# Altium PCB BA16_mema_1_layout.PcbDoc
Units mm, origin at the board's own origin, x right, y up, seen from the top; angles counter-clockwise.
Board outline 42 x 70 mm, 2 copper layers (Top Layer, Bottom Layer); 44 components, 23 nets, 138 pads, 178 vias.
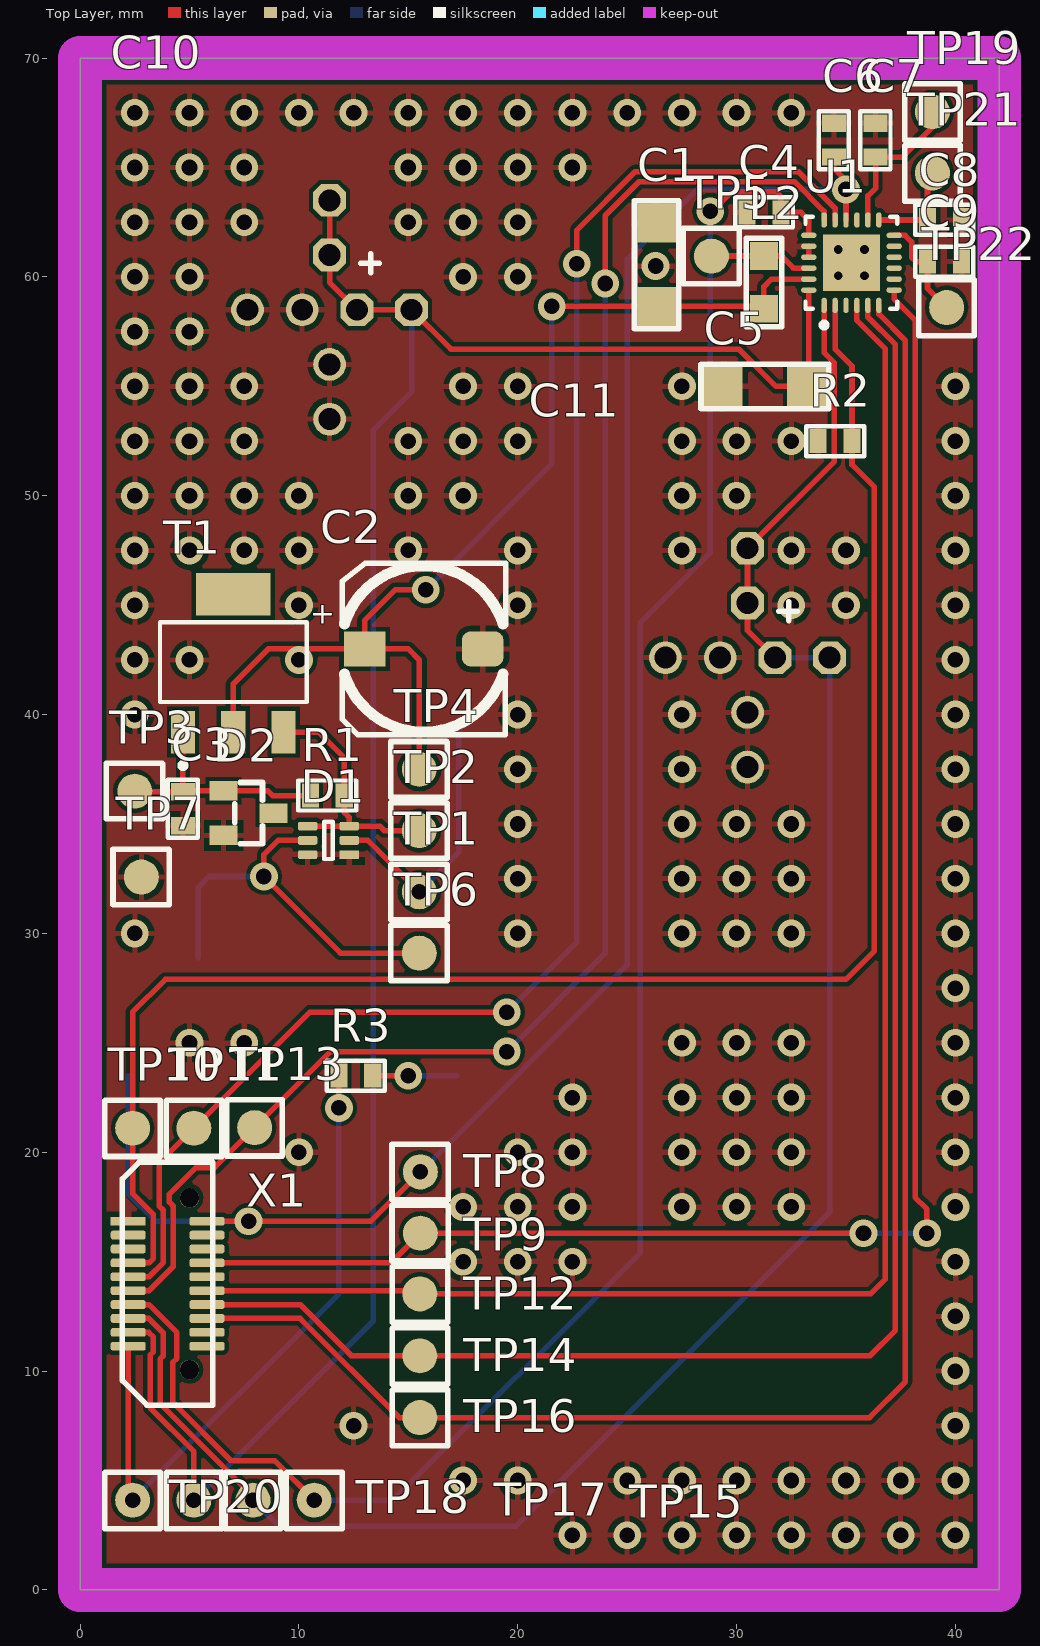
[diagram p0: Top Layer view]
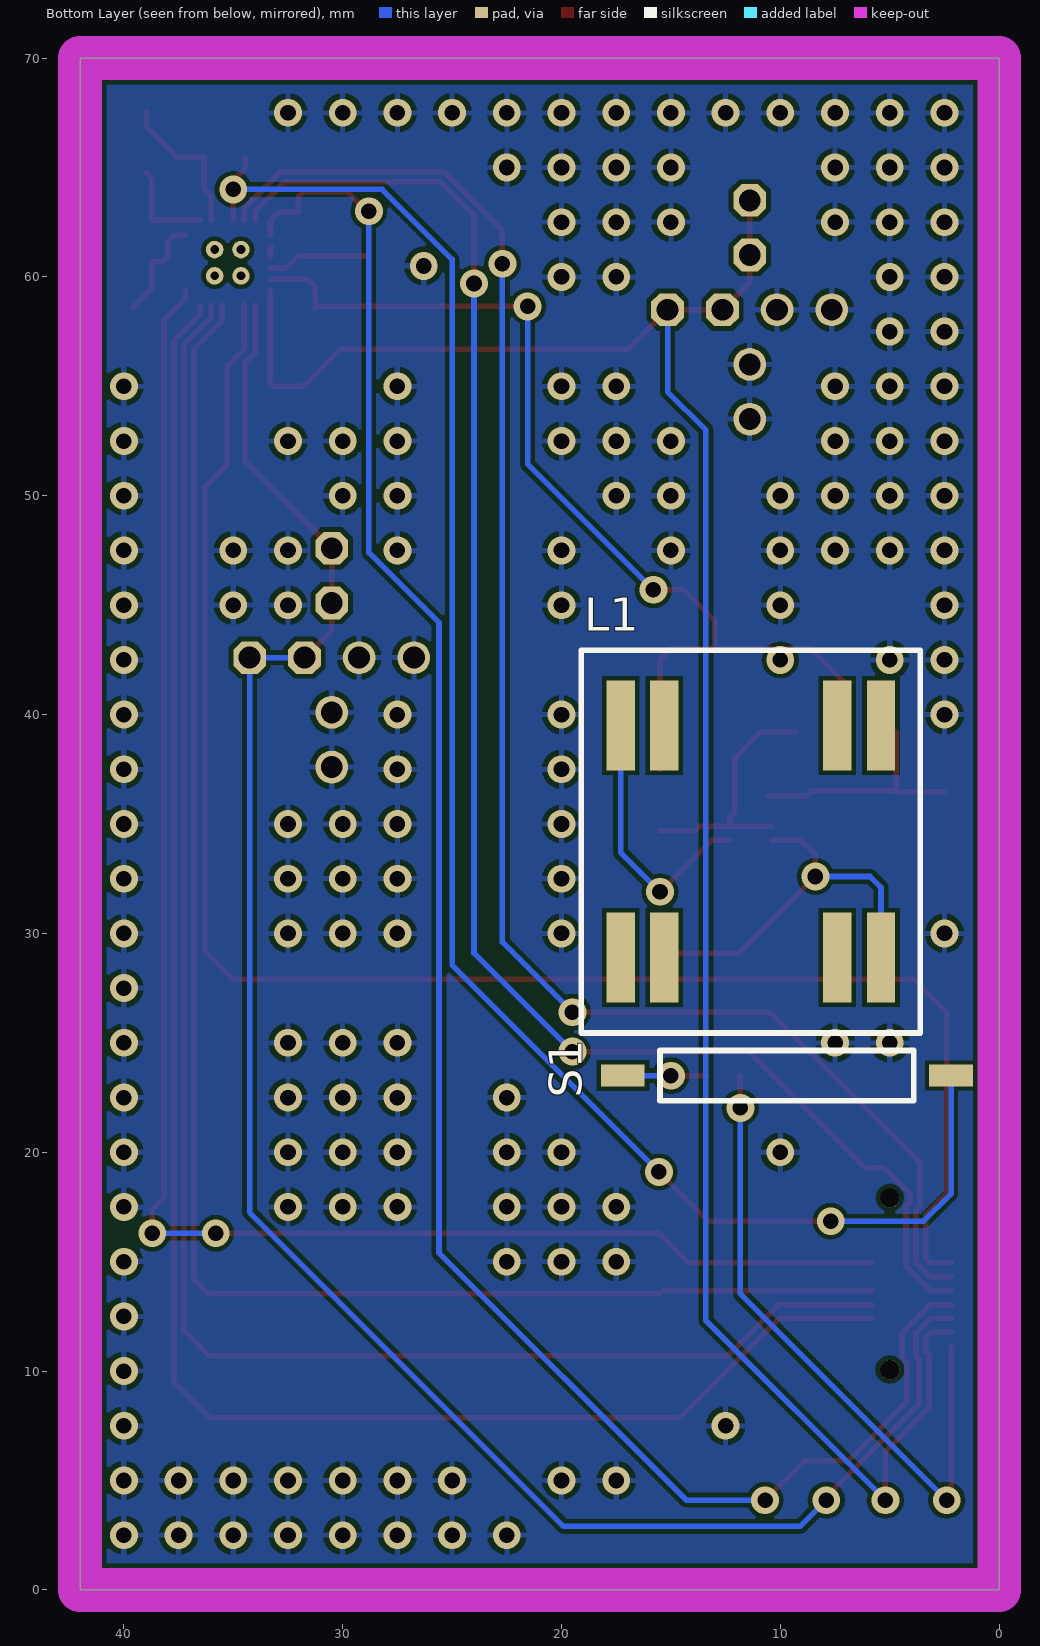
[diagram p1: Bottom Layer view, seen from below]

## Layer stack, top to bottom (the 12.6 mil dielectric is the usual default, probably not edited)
Top Solder: solder mask 0.0102, Solder Resist, Dk 3.5
Top Layer: signal copper 0.0356
Dielectric 1: dielectric 0.32, FR-4, Dk 4.8
Bottom Layer: signal copper 0.0356
Bottom Solder: solder mask 0.0102, Solder Resist, Dk 3.5

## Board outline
0,0 0,70 42,70 42,0

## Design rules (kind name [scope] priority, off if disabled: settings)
Clearance Clearance_EM8500 [All] p1: gap=0.2
Clearance [All] p2: gap=0.254
ComponentClearance ComponentClearance_ELKO_FLEX [HasFootprint('C_RAD_flex')] p1: gap=-5 collisioncheckmode=3 verticalgap=0.254 showdistances=FALSE
ComponentClearance ComponentClearance_TP [HasFootprint('TP SMD')] p2: gap=0 collisioncheckmode=3 verticalgap=0 showdistances=FALSE
ComponentClearance [All] p3: gap=0.254 collisioncheckmode=3 verticalgap=0.254 showdistances=FALSE
PolygonConnect [All] p1: connectstyle=Relief reliefconductorwidth=0.254 reliefentries=4 polygonreliefangle="90 Angle" airgapwidth=0.254
RoutingVias [All] p1: holewidth=0.711 width=1.27 viastyle="Through Hole" minholewidth=0.711 minwidth=1.27 maxholewidth=0.711 maxwidth=1.27
SilkToSilkClearance SilkToSilkClearance_TP [HasFootprint('TP SMD')] p1: silktosilkclearance=0
SilkToSilkClearance [All] p2: silktosilkclearance=0.254
SolderMaskExpansion [All] p1: expansion=0.102
Width [All] p1: maxlimit=0.254 minlimit=0.254 preferedwidth=0.254
28 further rules are at their usual default settings.

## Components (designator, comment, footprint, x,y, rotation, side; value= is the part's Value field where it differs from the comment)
C1 "Cap" "CHIP 1206" 26.35,58.65 r90 top
C2 "47uF 25V" "ELKO SMD-C 6.3x6.3" 15.7,43 r0 top
C3 "1nF" "CHIP 0603" 4.7,35.7 r90 top
C4 "Cap" "CHIP 0603" 31.25,62.95 r180 top
C5 "Cap" "CHIP 1206" 33.2,55 r180 top
C6 "Cap" "CHIP 0603" 34.45,66.25 r90 top
C7 "Cap" "CHIP 0603" 36.35,66.25 r90 top
C8 "Cap" "CHIP 0603" 39.5,62.6 r0 top
C9 "Cap" "CHIP 0603" 39.5,60.7 r0 top
C10 "3300uF 25V" C_RAD_FLEX 11.4,58.5 r0 top
C11 "470uF 25V" C_RAD_FLEX 30.5,42.6 r0 top
D1 "HSMS-286P" "SOT-363 (SC-70)" 12.3,33.6 r180 top
D2 "BAS16" SOT-23 7.7,35.5 r270 top
L1 "X-Wicklung" PREMO_3115N_0238J_2 17.3,28.9 r90 bottom
L2 "L" "CHIP 0805" 31.25,59.75 r270 top
R1 "1M" "CHIP 0603" 11.3,36.3 r0 top
R2 "R" "CHIP 0603" 34.5,52.5 r180 top
R3 "10k 0603" "CHIP 0603" 12.6,23.5 r0 top
S1 "Reed Switch" MK16-C-2 9.7,23.5 r180 bottom
T1 "BSP149" SOT-223 4.7,39.2 r0 top
TP1 "TP_SMD" "TP SMD" 15.5,31.9 r0 top
TP2 "TP_SMD" "TP SMD" 15.5,34.7 r0 top
TP3 "TP_SMD" "TP SMD" 2.5,36.5 r0 top
TP4 "TP_SMD" "TP SMD" 15.5,37.5 r0 top
TP5 "TP_SMD" "TP SMD" 28.85,60.95 r0 top
TP6 "TP_SMD" "TP SMD" 15.5,29.1 r0 top
TP7 "TP_SMD" "TP SMD" 2.8,32.575 r0 top
TP8 "TP_SMD" "TP SMD" 15.55,19.1 r0 top
TP9 "TP_SMD" "TP SMD" 15.55,16.3 r0 top
TP10 "TP_SMD" "TP SMD" 2.4,21.1 r90 top
TP11 "TP_SMD" "TP SMD" 5.2,21.1 r90 top
TP12 "TP_SMD" "TP SMD" 15.525,13.525 r90 top
TP13 "TP_SMD" "TP SMD" 7.975,21.125 r90 top
TP14 "TP_SMD" "TP SMD" 15.525,10.7 r90 top
TP15 "TP_SMD" "TP SMD" 10.7,4.1 r90 top
TP16 "TP_SMD" "TP SMD" 15.525,7.875 r90 top
TP17 "TP_SMD" "TP SMD" 7.9,4.1 r90 top
TP18 "TP_SMD" "TP SMD" 5.2,4.1 r90 top
TP19 "TP_SMD" "TP SMD" 38.95,67.55 r90 top
TP20 "TP_SMD" "TP SMD" 2.4,4.1 r90 top
TP21 "TP_SMD" "TP SMD" 38.95,64.75 r90 top
TP22 "TP_SMD" "TP SMD" 39.6,58.6 r90 top
U1 "em8500" QFN-24 35.25,60.65 r90 top
X1 "LSS-110-01-F-DV-A-TR" "HEADER SMD 2X10 0.635MM" 2.2,16.85 r0 top locked

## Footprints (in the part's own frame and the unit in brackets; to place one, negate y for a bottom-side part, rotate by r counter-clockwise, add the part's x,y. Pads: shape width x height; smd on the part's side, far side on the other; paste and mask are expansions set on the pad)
C_RAD_FLEX [mm] "KONDENSATOR, AXIAL, Raster 5"
  oct 1.5x1.5 hole 1: 1(0,2.5) 1(0,5) 1(1.25,0) 1(3.75,0)
  round 1.5 hole 1: 2(-3.75,0) 2(-1.25,0) 2(0,-5) 2(0,-2.5)
  silkscreen extent 1.42,1.7 2.27,2.55
"CHIP 0603" [mil] "Chip 0603 Body 1.6x0.8mm"
  rect 31x43 smd: 1(-30.5,0) 2(30.5,0)
  silkscreen extent -52,-27 52,27
"CHIP 0805" [mil] "Chip 0805 Body 2.0x1.2mm"
  rect 50x50 smd: 1(-47.5,0) 2(47.5,0)
  silkscreen extent -80,-32 80,32
"CHIP 1206" [mil] "Chip 1206 Body 3.2x1.6mm"
  rect 70x70 smd: 1(0,0) 2(150,0)
  silkscreen extent -40,-40 190,40
"ELKO SMD-C 6.3x6.3" [mm] "Elko SMD Size C 6.3x6.3mm H = 5.5mm"
  rect 1.9x1.6 smd: 1(-2.7,0)
  rrect50% 1.9x1.6 smd: 2(2.7,0)
  silkscreen extent -3.72,-3.93 3.75,3.93
"HEADER SMD 2X10 0.635MM" [mm] "LSS-110-01-F-DV-A"
  round 0.89 hole 0.89 unplated: 0(2.8,-6.783) 0(2.8,1.068)
  rect 1.6x0.4 smd: 1(0,0)
  rrect50% 1.6x0.4 smd: 2(3.6,0) 3(0,-0.635) 4(3.6,-0.635) 5(0,-1.27) 6(3.6,-1.27) 7(0,-1.905) 8(3.6,-1.905) 9(0,-2.54) 10(3.6,-2.54) 11(0,-3.175) 12(3.6,-3.175) 13(0,-3.81) 14(3.6,-3.81) 15(0,-4.445) 16(3.6,-4.445) 17(0,-5.08) 18(3.6,-5.08) 19(0,-5.715) 20(3.6,-5.715)
  silkscreen extent -0.27,-8.4 3.87,2.69
MK16-C-2 [mm] "REED SENSOR"
  rect 2x1 smd: 1(-7.5,0) 2(7.5,0)
  silkscreen extent -5.8,-1.15 5.8,1.15
PREMO_3115N_0238J_2 [mm] "3D Coil 15x15 2.38mH +/-5% @125kHz"
  rect 4.1x1.3 smd: 1(0,0) 2(0,-2) 3(0,-9.9) 4(0,-11.9) 5(10.6,-11.9) 6(10.6,-9.9) 7(10.6,-2) 8(10.6,0)
  silkscreen extent -3.45,-13.7 14.05,1.8
QFN-24 [mm] "24-Pin Plastic Quad Flat No-Lead 0.5 mm Pitch"
  oval 0.7x0.25 smd: 1(-1.95,1.25) 2(-1.95,0.75) 3(-1.95,0.25) 4(-1.95,-0.25) 5(-1.95,-0.75) 6(-1.95,-1.25) 13(1.95,-1.25) 14(1.95,-0.75) 15(1.95,-0.25) 16(1.95,0.25) 17(1.95,0.75) 18(1.95,1.25)
  oval 0.25x0.7 smd: 7(-1.25,-1.95) 8(-0.75,-1.95) 9(-0.25,-1.95) 10(0.25,-1.95) 11(0.75,-1.95) 12(1.25,-1.95) 19(1.25,1.95) 20(0.75,1.95) 21(0.25,1.95) 22(-0.25,1.95) 23(-0.75,1.95) 24(-1.25,1.95)
  round 0.8 hole 0.4: 25(-0.6,-0.6) 25(-0.6,0.6) 25(0.6,-0.6) 25(0.6,0.6)
  rect 2.6x2.6 smd: 25(0,0)
  silkscreen extent -2.97,-2.1 2.1,2.1, body extent -2.07,-2.07 2.07,2.07, height 1
SOT-23 [mil]
  rect 35x50 smd: 1(-40,-45) 2(40,-45) 3(0,45)
  silkscreen extent -55,-25 55,25
SOT-223 [mm] "SOT-223/SC-73; 4 Leads; Body 6.7 x 7.3 mm, inc. leads (LxW max)"
  rect 1.1x1.95 smd: 1(0,0) 2(2.3,0) 3(4.6,0)
  rect 3.4x1.95 smd: 4(2.3,6.3)
  silkscreen extent -1.05,-1.65 5.65,5.02
"SOT-363 (SC-70)" [mm]
  rect 0.9x0.4 smd: 1(0,0)
  rrect50% 0.9x0.4 smd: 2(0,-0.65) 3(0,-1.3) 4(1.9,-1.3) 5(1.9,-0.65) 6(1.9,0)
  silkscreen extent 0.75,-1.5 1.15,0.2
"TP SMD" [mm] "Testpoint SMD"
  round 1.6 smd: 1(0,0)
  silkscreen extent -1.3,-1.27 1.27,1.27

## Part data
C1 C4 C5 C6 C7 C8 C9: library part C, "Capacitor"
C2 C10 C11: library part "C POL", "Capasitor Polarisiert"
C3: library part "C 50V", "Capacitor 50V"
D1: "Diode Schottky Quadro"
D2: library part D, "Diode"
L1: library part "PREMO 3015 0238J 2", "Inductor"
L2: "Ind"
R1 R3: library part R, "Resistor"
R2: "Resistor"
S1: library part "SWITCH MICRO NO", "Switch Micro Normal Open"
T1: "MOSFET N-Kanal"
TP1 TP2 TP3 TP4 TP5 TP6 TP7 TP8 TP9 TP10 TP11 TP12 TP13 TP14 TP15 TP16 TP17 TP18 TP19 TP20 TP21 TP22: "Testpoint SMD"
X1: library part "HDR 20 POL ABW", "Header 100 mil 20 Pol"

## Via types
v1: diameter 1.27, hole 0.711, Top Layer to Bottom Layer, 178 vias

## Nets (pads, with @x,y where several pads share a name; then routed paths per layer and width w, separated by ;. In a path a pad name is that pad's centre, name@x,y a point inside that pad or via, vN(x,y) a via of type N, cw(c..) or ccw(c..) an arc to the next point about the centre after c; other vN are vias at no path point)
BAT_LOW: TP13.1 U1.18 X1.11 | length 75.7
  Top Layer w0.254: X1.11 3.159,13.675 4.258,14.774 4.258,17.539 4.079,17.718 4.079,18.088 5.291,19.3 6.15,19.3 TP13.1 11.45,24.6 v1(19.5,24.6) ; v1(24,59.7) 24,62.8 25.551,64.351 32.646,64.351 34,62.997 U1.18
  Bottom Layer w0.254: v1(19.5,24.6) 24,29.1 v1(24,59.7)
EM_CS: TP9.1 U1.7 X1.8 | length 77.2
  Top Layer w0.254: X1.8 14.195,14.945 TP9.1 v1(35.8,16.3) ; U1.7 37.2,59 38.162,58.038 38.162,17.938 38.7,17.4 v1(38.7,16.3)
  Bottom Layer w0.254: v1(35.8,16.3) v1(38.7,16.3)
GND: C1.2 C2.2 C3.1 C4.2 C5.2 C6.2 C7.2 C8.2 C9.2 C10.2 C11.2 D1.1 D1.6 D2.2 R2.2 TP7.1 U1.20 U1.21 X1.1 | length 0.5
  Top Layer w0.254: U1.21 U1.20
  other v1: 22.5,2.5 25,2.5 27.5,2.5 30,2.5 32.5,2.5 35,2.5 37.5,2.5 40,2.5 17.5,5 20,5 25,5 27.5,5 30,5 32.5,5 35,5 37.5,5 40,5 12.5,7.5 40,7.5 40,10 40,12.5 17.5,15 20,15 22.5,15 40,15 17.5,17.5 20,17.5 22.5,17.5 27.5,17.5 30,17.5 32.5,17.5 40,17.5 10,20 20,20 22.5,20 27.5,20 30,20 32.5,20 40,20 22.5,22.5 27.5,22.5 30,22.5 32.5,22.5 40,22.5 5,25 7.5,25 27.5,25 27.5,25 30,25 32.5,25 40,25 40,25 40,27.5 2.5,30 20,30 27.5,30 30,30 32.5,30 40,30 20,32.5 27.5,32.5 30,32.5 32.5,32.5 40,32.5 20,35 27.5,35 30,35 32.5,35 40,35 40,35 40,35 20,37.5 27.5,37.5 40,37.5 2.5,40 20,40 27.5,40 40,40 2.5,42.5 5,42.5 40,42.5 2.5,45 10,45 20,45 32.5,45 35,45 40,45 2.5,47.5 5,47.5 7.5,47.5 10,47.5 15,47.5 20,47.5 27.5,47.5 32.5,47.5 35,47.5 40,47.5 2.5,50 2.5,50 5,50 7.5,50 10,50 15,50 17.5,50 27.5,50 30,50 40,50 2.5,52.5 5,52.5 7.5,52.5 15,52.5 17.5,52.5 20,52.5 27.5,52.5 30,52.5 32.5,52.5 40,52.5 2.5,55 5,55 7.5,55 17.5,55 20,55 27.5,55 40,55 2.5,57.5 5,57.5 2.5,60 5,60 17.5,60 20,60 26.3,60.5 2.5,62.5 5,62.5 7.5,62.5 15,62.5 17.5,62.5 20,62.5 2.5,65 5,65 7.5,65 15,65 17.5,65 20,65 22.5,65 2.5,67.5 5,67.5 7.5,67.5 10,67.5 12.5,67.5 15,67.5 17.5,67.5 20,67.5 22.5,67.5 25,67.5 27.5,67.5 30,67.5 32.5,67.5
HRV_LOW: TP11.1 U1.17 X1.9 | length 76.4
  Top Layer w0.254: X1.9 3.152,14.31 3.804,14.962 3.804,17.35 3.625,17.529 3.625,19.525 TP11.1 10.5,26.4 v1(19.5,26.4) ; v1(22.7,60.6) 22.7,62.142 25.363,64.805 32.834,64.805 34.5,63.14 U1.17
  Bottom Layer w0.254: v1(19.5,26.4) 22.7,29.6 v1(22.7,60.6)
MCU_MISO: TP14.1 U1.5 X1.14 | length 80.3
  Top Layer w0.254: X1.14 10.06,13.04 12.4,10.7 TP14.1 36.1,10.7 37.254,11.854 37.254,56.904 36,58.158 U1.5
MCU_MOSI: TP12.1 U1.4 X1.12 | length 76.2
  Top Layer w0.254: X1.12 TP12.1@15.375,13.675 ; TP12.1 36.125,13.525 36.8,14.2 36.8,56.716 35.5,58.016 U1.4
MCU_SCLK: TP16.1 U1.6 X1.16 | length 84.2
  Top Layer w0.254: X1.16 10.053,12.405 14.583,7.875 TP16.1 36.075,7.875 37.708,9.508 37.708,57.092 36.5,58.3 U1.6
NetC3_2: C3.2 D2.1 R1.1 T1.1 TP3.1 | length 10.8
  Top Layer w0.254: TP3.1@2.525,36.475 C3.2 T1.1 ; C3.2@4.741,36.516 D2.1 8.584,36.516 8.8,36.3 R1.1
NetD1_2: D1.2 L1.8 TP1.1 | length 12.5
  Top Layer w0.254: D1.2 13.15,34.25 v1(15.5,31.9)
  Bottom Layer w0.254: v1(15.5,31.9) 17.3,33.7 L1.8
NetD1_3: D1.3 D1.4 R1.2 T1.3 TP2.1 | length 11.7
  Top Layer w0.254: T1.3 10.9,39.2 12.075,38.025 R1.2 12.075,35.525 12.3,35.3 D1.3 ; D1.4 D1.3 ; TP2.1 13.9,34.7 13.7,34.9 D1.3
NetD1_5: D1.5 L1.4 TP6.1 | length 18.2
  Top Layer w0.254: D1.5 9.05,34.25 8.4,33.6 v1(8.4,32.6) 11.9,29.1 TP6.1
  Bottom Layer w0.254: L1.4 5.4,32.1 5.9,32.6 v1(8.4,32.6)
NetL2_1: L2.1 TP5.1 U1.22 | length 4.7
  Top Layer w0.254: TP5.1@28.857,60.956 L2.1 32.044,60.956 32.6,60.4 U1.22
NetR3_2: R3.2 S1.1 | length 3.8
  Top Layer w0.254: R3.2 v1(15,23.5)
  Bottom Layer w0.254: v1(15,23.5) S1.1
REED_SWITCH: R3.1 TP20.1 X1.19 | length 30.1
  Top Layer w0.254: TP20.1@2.2,4.3 X1.19 ; v1(11.825,22.025) R3.1
  Bottom Layer w0.254: v1(2.4,4.1) 11.825,13.525 v1(11.825,22.025)
VAUX_VCC0: C9.1 TP22.1 U1.12 | length 4.9
  Top Layer w0.254: U1.12 37.7,61.9 38,61.6 38,60.9 38.2,60.7 C9.1 38.725,59.475 TP22.1
VAUX_VCC1: C8.1 TP21.1 U1.13 | length 4.5
  Top Layer w0.254: U1.13 C8.1 38.725,64.525 TP21.1
VAUX_VCC2: C7.1 TP19.1 U1.14 | length 6.9
  Top Layer w0.254: U1.14 36,63.7 36.35,64.05 C7.1 37.575,65.475 38.95,66.85 TP19.1
VCC: C1.1 C2.1 L2.2 T1.2 TP4.1 U1.23 | length 49.4
  Top Layer w0.254: T1.2 7,41.4 8.6,43 C2.1 ; TP4.1 15.5,42.5 15,43 C2.1 ; v1(15.8,45.7) 14.4,45.7 13,44.3 C2.1 ; v1(21.55,58.65) C1.1 L2.2@31.144,58.65 ; L2.2 31.25,59.55 31.6,59.9 U1.23
  Bottom Layer w0.254: v1(15.8,45.7) 21.55,51.45 v1(21.55,58.65)
  other v1: 10,42.5
VCC_LTS: C5.1 C10.1 TP18.1 U1.24 X1.17 | length 99.9
  Top Layer w0.254: X1.17 3.13,11.77 3.346,11.554 3.346,10.877 3.2,10.731 3.2,8.325 5.2,6.325 v1(5.2,4.1) ; C10.1@11.4,63.5 11.4,61 11.4,59.75 12.65,58.5 15.15,58.5 16.95,56.7 30.1,56.7 31.8,55 C5.1 ; C5.1@33.3,55.1 U1.24
  Bottom Layer w0.254: v1(5.2,4.1) 13.4,12.3 13.4,33.56 13.4,53 15.15,54.75 C10.1@15.15,58.5
VCC_STS: C11.1 TP17.1 U1.1 X1.15 | length 90.3
  Top Layer w0.254: X1.15 3.137,12.405 3.8,11.742 3.8,10.689 3.654,10.543 3.654,8.513 TP17.1@7.9,4.267 ; C11.1@31.75,42.6 30.5,43.85 30.5,45.1 30.5,47.6 34.466,51.566 34.466,56.074 34,56.54 U1.1
  Bottom Layer w0.254: v1(7.9,4.1) 9.1,2.9 19.9,2.9 34.25,17.25 34.25,42.6 C11.1@31.75,42.6
VREG: C4.1 TP15.1 U1.19 X1.13 | length 89.4
  Top Layer w0.254: X1.13 3.144,13.04 4.425,11.759 4.425,10.584 4.228,10.387 4.228,8.581 6.909,5.9 8.9,5.9 v1(10.7,4.1) ; v1(28.8,63) 28.9,63 29.797,63.897 31.803,63.897 32.025,63.675 C4.1 32.95,62.95 33.3,62.6 U1.19
  Bottom Layer w0.254: v1(10.7,4.1) 14.3,4.1 25.6,15.4 25.6,44.2 28.8,47.4 v1(28.8,63)
VSUP: C6.1 S1.2 TP8.1 U1.16 X1.2 | length 82.1
  Top Layer w0.254: X1.2 v1(7.7,16.85) 13.3,16.85 v1(15.55,19.1) ; C6.1 34.45,64.95 35,64.4 U1.16
  Bottom Layer w0.254: S1.2 2.2,18.1 3.45,16.85 v1(7.7,16.85) ; v1(15.55,19.1) 25,28.55 25,60.8 28.2,64 v1(35,64)
WAKE_UP: R2.1 TP10.1 U1.2 X1.7 | length 78.2
  Top Layer w0.254: X1.7 3.145,14.945 3.35,15.15 3.35,17.162 2.4,18.112 TP10.1 2.4,26.4 3.9,27.9 35,27.9 36.3,29.2 36.3,50.4 35.275,51.425 R2.1 35.275,55.924 34.5,56.698 U1.2
pads on no net: D2.3 L1.1 L1.2 L1.3 L1.5 L1.6 L1.7 T1.4 U1.3 U1.8 U1.9 U1.10 U1.11 U1.15 U1.25 X1.0 X1.3 X1.4 X1.5 X1.6 X1.10 X1.18 X1.20

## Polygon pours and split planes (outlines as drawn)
GND on Top Layer "Top Layer-GND" (solid, remove dead copper, pour order 2): 0,70 0,0 42,0 42,70
GND on Bottom Layer "Bottom Layer-GND" (solid, remove dead copper, pour order 4): 0,70 0,0 42,0 42,70

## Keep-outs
Top Layer:
  the board outline again, w2
Bottom Layer:
  the board outline again, w2

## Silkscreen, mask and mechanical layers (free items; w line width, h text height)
Mechanical 1:
  lines w0.254: 0,8.45 42,8.45 ; 0,19.55 42,19.55 ; 0,32 42,32 ; 1.91,0 1.91,70 ; 0,0 42,0 42,70 0,70 0,0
